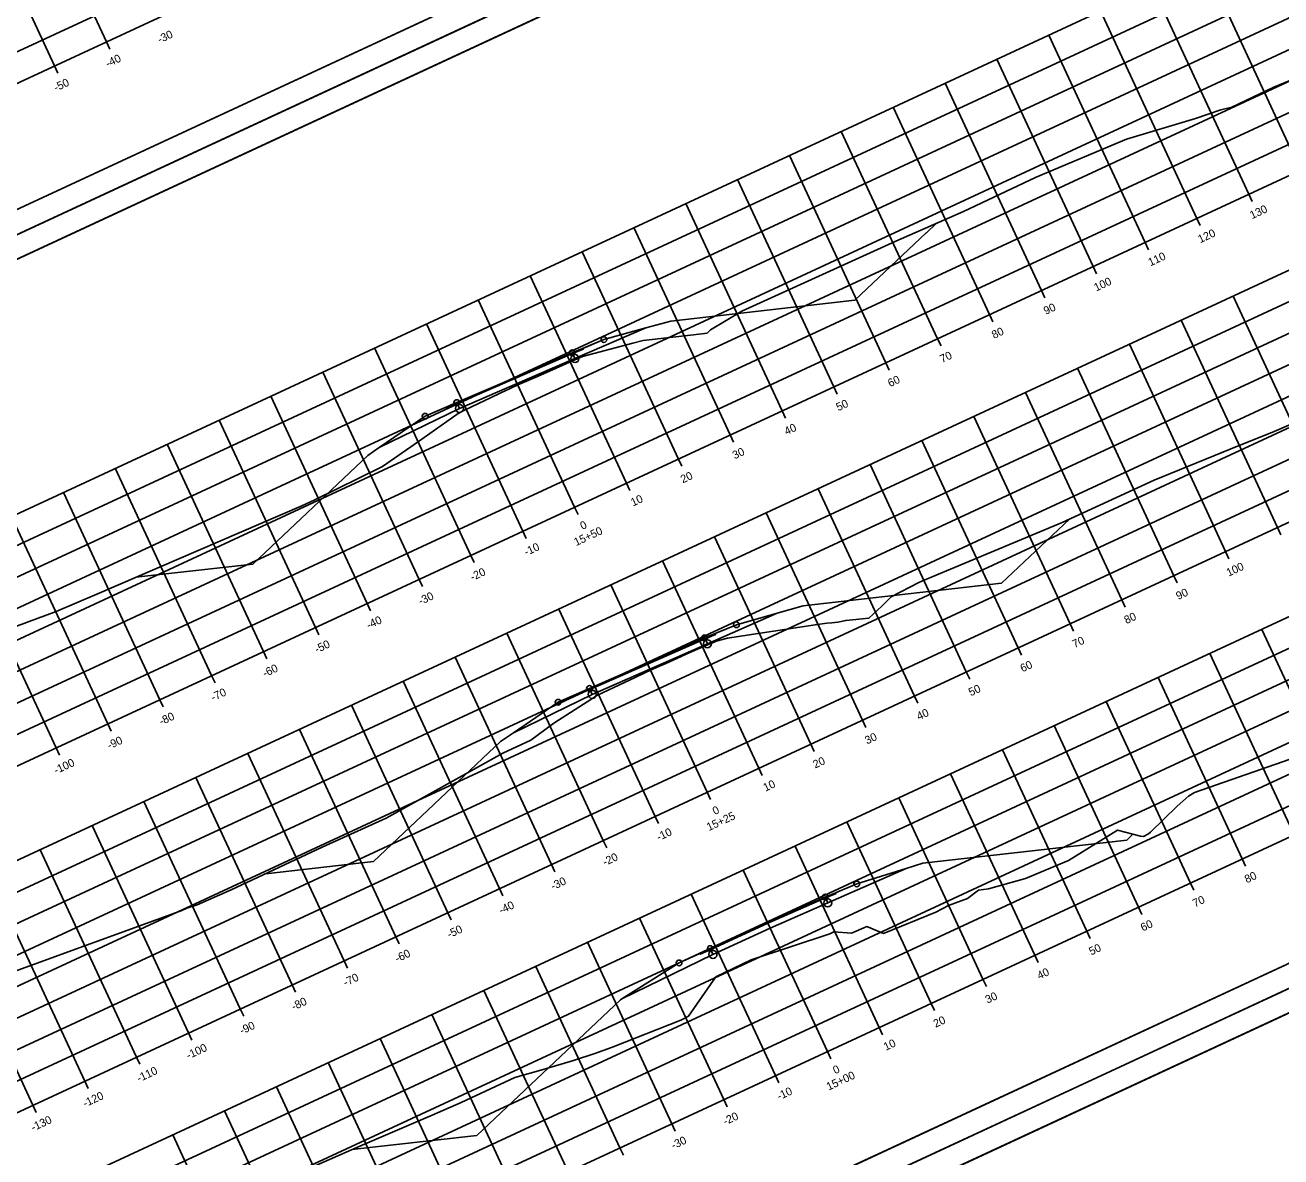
# Model space of a CAD drawing. Extents: x 1354696 to 1366163, y 660729 to 670380.
# Drawn here: x 1358777 to 1358996.6, y 665980.8 to 666178.8 of the extents above; entities that cross this region are included whole.
import ezdxf

# ---------------------------------------------------------------- set-up
doc = ezdxf.new("R2010")
doc.units = 0
for name, color, linetype in [('R_Alt Surface', 7, 'Continuous'), ('R_Axis', 7, 'Continuous'), ('R_Axis Annot', 7, 'Continuous'), ('R_Border', 7, 'Continuous'), ('R_Exist Surface', 7, 'Continuous'), ('R_Fin Surface', 7, 'Continuous'), ('R_Grid', 7, 'Continuous'), ('R_No Plot', 7, 'Continuous')]:
    doc.layers.add(name, color=color, linetype=linetype)

msp = doc.modelspace()

# ---------------------------------------------------------------- linework, layer by layer
at = {"layer": 'R_Alt Surface'}
for p, q in [((1358872.65, 666121.46), (1358874.5, 666122.23)), ((1358872.72, 666121.31), (1358874.57, 666122.08)), ((1358850.62, 666111.95), (1358852.45, 666112.74)), ((1358850.69, 666111.8), (1358852.52, 666112.59)), ((1358895.81, 666071.58), (1358897.66, 666072.34)), ((1358895.88, 666071.42), (1358897.73, 666072.19)), ((1358873.85, 666061.92), (1358875.67, 666062.72)), ((1358873.92, 666061.77), (1358875.74, 666062.57)), ((1358916.87, 666026.22), (1358918.72, 666026.99)), ((1358916.94, 666026.07), (1358918.79, 666026.84)), ((1358894.97, 666016.37), (1358896.8, 666017.21)), ((1358895.04, 666016.22), (1358896.87, 666017.06))]:
    msp.add_line(p, q, dxfattribs=at)
for points in [[(1358838.9, 666104.87), (1358852.92, 666111.72), (1358863.02, 666116.08), (1358873.13, 666120.44), (1358885.55, 666125.8)], [(1358852.45, 666112.74), (1358862.55, 666117.1), (1358872.65, 666121.46)], [(1358852.52, 666112.59), (1358862.62, 666116.95), (1358872.72, 666121.31)], [(1358862.36, 666054.97), (1358876.14, 666061.7), (1358886.21, 666066.13), (1358896.29, 666070.56), (1358908.5, 666075.92)], [(1358875.67, 666062.72), (1358885.74, 666067.15), (1358895.81, 666071.58)], [(1358875.74, 666062.57), (1358885.81, 666067), (1358895.88, 666071.42)], [(1358881.34, 666008.4), (1358897.27, 666016.19), (1358907.27, 666020.77), (1358917.34, 666025.2), (1358931.06, 666031.24)], [(1358896.8, 666017.21), (1358906.8, 666021.79), (1358916.87, 666026.22)], [(1358896.87, 666017.06), (1358906.87, 666021.64), (1358916.94, 666026.07)]]:
    msp.add_lwpolyline(points, dxfattribs=at)
for points in [[(1358874.5, 666122.23), (1358874.57, 666122.08), (1358872.72, 666121.31), (1358873.13, 666120.44), (1358885.55, 666125.8), (1358878.2, 666123.77)], [(1358850.62, 666111.95), (1358850.69, 666111.8), (1358852.52, 666112.59), (1358852.92, 666111.72), (1358838.9, 666104.87), (1358846.93, 666110.36)], [(1358897.66, 666072.34), (1358897.73, 666072.19), (1358895.88, 666071.42), (1358896.29, 666070.56), (1358908.5, 666075.92), (1358901.36, 666073.88)], [(1358873.85, 666061.92), (1358873.92, 666061.77), (1358875.74, 666062.57), (1358876.14, 666061.7), (1358862.36, 666054.97), (1358870.17, 666060.31)], [(1358918.72, 666026.99), (1358922.41, 666028.53), (1358931.06, 666031.24), (1358917.34, 666025.2), (1358916.94, 666026.07), (1358918.79, 666026.84)], [(1358894.97, 666016.37), (1358895.04, 666016.22), (1358896.87, 666017.06), (1358897.27, 666016.19), (1358881.34, 666008.4), (1358891.34, 666014.71)]]:
    msp.add_lwpolyline(points, close=True, dxfattribs=at)
at = {"layer": 'R_Axis'}
for p, q in [((1358691.39, 666129.54), (1358963.5, 666255.87)), ((1358791.76, 666174.59), (1358791.17, 666175.86)), ((1358782.69, 666170.38), (1358782.1, 666171.65)), ((1358737.02, 666031.28), (1359009.12, 666157.61)), ((1358991.57, 666147.92), (1358990.98, 666149.19)), ((1358982.5, 666143.71), (1358981.91, 666144.98)), ((1358973.43, 666139.5), (1358972.84, 666140.77)), ((1358964.36, 666135.28), (1358963.77, 666136.55)), ((1358955.29, 666131.07), (1358954.7, 666132.34)), ((1358946.22, 666126.86), (1358945.63, 666128.13)), ((1358937.15, 666122.65), (1358936.56, 666123.92)), ((1358928.08, 666118.44), (1358927.49, 666119.71)), ((1358919.01, 666114.23), (1358918.42, 666115.5)), ((1358909.94, 666110.02), (1358909.35, 666111.29)), ((1358760.18, 665981.39), (1359032.28, 666107.72)), ((1358900.87, 666105.81), (1358900.28, 666107.08)), ((1358891.8, 666101.6), (1358891.21, 666102.87)), ((1358882.73, 666097.39), (1358882.14, 666098.65)), ((1358873.66, 666093.17), (1358873.07, 666094.44)), ((1358864.59, 666088.96), (1358864, 666090.23)), ((1358996.59, 666089.61), (1358996, 666090.88)), ((1358855.52, 666084.75), (1358854.93, 666086.02)), ((1358987.52, 666085.4), (1358986.93, 666086.67)), ((1358978.45, 666081.19), (1358977.86, 666082.46)), ((1358846.45, 666080.54), (1358845.86, 666081.81)), ((1358969.38, 666076.98), (1358968.79, 666078.25)), ((1358837.38, 666076.33), (1358836.79, 666077.6)), ((1358960.31, 666072.77), (1358959.72, 666074.04)), ((1358828.31, 666072.12), (1358827.72, 666073.39)), ((1358951.24, 666068.55), (1358950.65, 666069.82)), ((1358819.24, 666067.91), (1358818.65, 666069.18)), ((1358810.17, 666063.7), (1358809.58, 666064.97)), ((1358942.17, 666064.34), (1358941.58, 666065.61)), ((1358781.23, 665936.04), (1359053.34, 666062.37)), ((1358801.1, 666059.49), (1358800.51, 666060.76)), ((1358933.1, 666060.13), (1358932.51, 666061.4)), ((1358792.03, 666055.27), (1358791.44, 666056.54)), ((1358924.03, 666055.92), (1358923.44, 666057.19)), ((1358782.96, 666051.06), (1358782.37, 666052.33)), ((1358914.96, 666051.71), (1358914.37, 666052.98)), ((1358905.89, 666047.5), (1358905.3, 666048.77)), ((1358896.82, 666043.29), (1358896.23, 666044.56)), ((1358887.75, 666039.08), (1358887.16, 666040.35)), ((1358878.68, 666034.87), (1358878.09, 666036.14)), ((1358869.61, 666030.66), (1358869.02, 666031.93)), ((1358990.43, 666031.63), (1358989.84, 666032.9)), ((1358860.54, 666026.44), (1358859.95, 666027.71)), ((1358981.36, 666027.41), (1358980.77, 666028.68)), ((1358851.47, 666022.23), (1358850.88, 666023.5)), ((1358972.29, 666023.2), (1358971.7, 666024.47)), ((1358842.4, 666018.02), (1358841.81, 666019.29)), ((1358963.22, 666018.99), (1358962.63, 666020.26)), ((1358833.33, 666013.81), (1358832.74, 666015.08)), ((1358954.15, 666014.78), (1358953.56, 666016.05)), ((1358824.26, 666009.6), (1358823.67, 666010.87)), ((1358945.08, 666010.57), (1358944.49, 666011.84)), ((1358815.19, 666005.39), (1358814.6, 666006.66)), ((1358936.01, 666006.36), (1358935.42, 666007.63)), ((1358926.94, 666002.15), (1358926.35, 666003.42)), ((1358806.12, 666001.18), (1358805.53, 666002.45)), ((1358917.87, 665997.94), (1358917.28, 665999.21)), ((1358797.05, 665996.97), (1358796.46, 665998.24)), ((1358908.8, 665993.73), (1358908.21, 665995)), ((1358787.98, 665992.76), (1358787.39, 665994.03)), ((1358899.73, 665989.52), (1358899.14, 665990.79)), ((1358778.91, 665988.55), (1358778.32, 665989.81)), ((1358890.66, 665985.3), (1358890.07, 665986.57)), ((1358881.59, 665981.09), (1358881, 665982.36))]:
    msp.add_line(p, q, dxfattribs=at)
at = {"layer": 'R_Border'}
for p, q in [((1358979.34, 666241.18), (1358692.56, 666108.03)), ((1358695.88, 666100.89), (1358982.66, 666234.03)), ((1358834.33, 666164.88), (1358834.33, 666164.88)), ((1358834.33, 666164.88), (1358834.33, 666164.88)), ((1359069.18, 666047.68), (1358782.4, 665914.53)), ((1358785.71, 665907.39), (1359072.49, 666040.53))]:
    msp.add_line(p, q, dxfattribs=at)
at = {"layer": 'R_Exist Surface'}
for points in [[(1358738.8, 666060.04), (1358782.36, 666076.2), (1358789.49, 666079.23), (1358825.33, 666094.7), (1358827.64, 666095.74), (1358839.45, 666101.55), (1358845.74, 666105.92), (1358852.71, 666110.84), (1358853.68, 666111.35), (1358853.8, 666111.41), (1358857.36, 666113.09), (1358857.73, 666113.26), (1358858, 666113.39), (1358860.42, 666114.58), (1358860.69, 666114.7), (1358863.15, 666115.83), (1358863.15, 666115.83), (1358863.41, 666115.95), (1358865.9, 666117.04), (1358866.15, 666117.16), (1358868.66, 666118.22), (1358872.16, 666119.83), (1358872.52, 666119.99), (1358872.7, 666120.07), (1358874.44, 666120.79), (1358883.25, 666123.12), (1358885.04, 666123.59), (1358893.85, 666124.6), (1358896.25, 666124.87), (1358896.85, 666125.49), (1358902.34, 666128.75), (1358929.27, 666140.97), (1358941.06, 666146.15), (1358953.8, 666152.18), (1358969.61, 666158.84), (1358981.67, 666162.47), (1358986.08, 666163.98), (1358988.04, 666164.42), (1358995.36, 666167.94), (1358998.36, 666169.14)], [(1358761.71, 666008.36), (1358804.35, 666023.91), (1358805.24, 666024.3), (1358807.07, 666024.89), (1358812.97, 666027.5), (1358828.92, 666034.98), (1358840.09, 666040.03), (1358860.5, 666051.38), (1358865.4, 666053.66), (1358869.43, 666056.66), (1358876.07, 666060.94), (1358876.25, 666061.04), (1358876.94, 666061.48), (1358879.93, 666062.88), (1358880.83, 666063.31), (1358882.89, 666064.3), (1358883.54, 666064.6), (1358885.6, 666065.6), (1358886.25, 666065.89), (1358888.34, 666066.81), (1358889, 666067.1), (1358891.08, 666068.04), (1358891.73, 666068.34), (1358892.71, 666068.79), (1358895.91, 666070.19), (1358897.48, 666070.84), (1358897.84, 666070.99), (1358899.79, 666071.5), (1358915.13, 666073.87), (1358917.19, 666074.18), (1358918.04, 666074.24), (1358919.11, 666074.33), (1358920.48, 666074.62), (1358924.54, 666075.02), (1358926.78, 666077.13), (1358928.42, 666078.78), (1358933.39, 666081.34), (1358933.66, 666081.44), (1358933.7, 666081.44), (1358933.81, 666081.5), (1358934.2, 666081.67), (1358958.33, 666091.76), (1358974.46, 666099.15), (1358987.72, 666104.62), (1358995.42, 666107.7), (1359003.14, 666111.04)], [(1358814.81, 665973.54), (1358835.53, 665982.66), (1358848.14, 665988.09), (1358853.22, 665990.27), (1358862.63, 665994.67), (1358867.54, 665996.07), (1358872.88, 665997.61), (1358876.63, 665998.89), (1358879.53, 665999.89), (1358891.63, 666004.7), (1358892.96, 666005.37), (1358897.79, 666012.26), (1358903.95, 666015.24), (1358917.7, 666019.79), (1358918.39, 666020.13), (1358921.5, 666019.92), (1358923.67, 666020.82), (1358924.16, 666021.06), (1358927.1, 666019.88), (1358936.24, 666023.61), (1358938.44, 666024.73), (1358941.79, 666025.96), (1358943.7, 666027.44), (1358945.46, 666027.7), (1358951.91, 666029.49), (1358959.46, 666032.6), (1358968.02, 666037.92), (1358972.04, 666036.86), (1358972.55, 666036.84), (1358973.47, 666037.31), (1358973.78, 666037.57), (1358978.48, 666042.13), (1358980.42, 666043.91), (1358981.48, 666044.5), (1359000.75, 666051.23)]]:
    msp.add_lwpolyline(points, dxfattribs=at)
at = {"layer": 'R_Fin Surface'}
for points in [[(1358796.34, 666082.18), (1358816.76, 666084.5), (1358836.89, 666103.5), (1358838.9, 666104.87), (1358846.93, 666110.36), (1358852.45, 666112.74), (1358862.55, 666117.1), (1358872.65, 666121.46), (1358878.2, 666123.77), (1358885.55, 666125.8), (1358889.92, 666127.01), (1358922.1, 666130.66), (1358934.58, 666142.43), (1358934.6, 666142.46), (1358936.3, 666144.06)], [(1358818.99, 666030.32), (1358837.9, 666032.47), (1358860.13, 666053.44), (1358862.36, 666054.97), (1358870.17, 666060.31), (1358875.67, 666062.72), (1358885.74, 666067.15), (1358895.81, 666071.58), (1358901.36, 666073.88), (1358908.5, 666075.92), (1358913.04, 666077.21), (1358947.73, 666081.15), (1358959.6, 666092.34)], [(1358834.12, 665982.04), (1358855.94, 665984.51), (1358881.11, 666008.26), (1358881.34, 666008.4), (1358891.34, 666014.71), (1358896.8, 666017.21), (1358906.8, 666021.79), (1358916.87, 666026.22), (1358922.41, 666028.53), (1358931.06, 666031.24), (1358933.96, 666032.15), (1358969.65, 666036.2), (1358970.72, 666037.21)]]:
    msp.add_lwpolyline(points, dxfattribs=at)
at = {"layer": 'R_Grid'}
for p, q in [((1358689.29, 666134.08), (1358961.39, 666260.41)), ((1358691.39, 666129.54), (1358963.5, 666255.87)), ((1358791.17, 666175.86), (1358774.32, 666212.14)), ((1358782.1, 666171.65), (1358765.25, 666207.93)), ((1358720.17, 666067.56), (1358992.28, 666193.89)), ((1358722.28, 666063.02), (1358994.38, 666189.35)), ((1359000.05, 666153.4), (1358983.21, 666189.68)), ((1358724.38, 666058.49), (1358996.49, 666184.82)), ((1358990.98, 666149.19), (1358974.14, 666185.47)), ((1358981.91, 666144.98), (1358965.07, 666181.26)), ((1358726.49, 666053.95), (1358998.59, 666180.28)), ((1358972.84, 666140.77), (1358956, 666177.05)), ((1358728.59, 666049.42), (1359000.7, 666175.75)), ((1358963.77, 666136.55), (1358946.93, 666172.83)), ((1358730.7, 666044.88), (1359002.8, 666171.21)), ((1358954.7, 666132.34), (1358937.86, 666168.62)), ((1358732.8, 666040.35), (1359004.91, 666166.68)), ((1358945.63, 666128.13), (1358928.78, 666164.41)), ((1358734.91, 666035.81), (1359007.01, 666162.14)), ((1358936.56, 666123.92), (1358919.71, 666160.2)), ((1358737.02, 666031.28), (1359009.12, 666157.61)), ((1358927.49, 666119.71), (1358910.64, 666155.99)), ((1358918.42, 666115.5), (1358901.57, 666151.78)), ((1358909.35, 666111.29), (1358892.5, 666147.57)), ((1358743.33, 666017.67), (1359015.44, 666144)), ((1358900.28, 666107.08), (1358883.43, 666143.36)), ((1358745.44, 666013.14), (1359017.54, 666139.47)), ((1358891.21, 666102.87), (1358874.36, 666139.15)), ((1358747.54, 666008.6), (1359019.65, 666134.93)), ((1358882.14, 666098.65), (1358865.29, 666134.94)), ((1359005.07, 666095.09), (1358988.23, 666131.37)), ((1358749.65, 666004.07), (1359021.75, 666130.4)), ((1358873.07, 666094.44), (1358856.22, 666130.72)), ((1358864, 666090.23), (1358847.15, 666126.51)), ((1358996, 666090.88), (1358979.16, 666127.16)), ((1358751.75, 665999.53), (1359023.86, 666125.86)), ((1358854.93, 666086.02), (1358838.08, 666122.3)), ((1358986.93, 666086.67), (1358970.09, 666122.95)), ((1358753.86, 665995), (1359025.96, 666121.33)), ((1358845.86, 666081.81), (1358829.01, 666118.09)), ((1358977.86, 666082.46), (1358961.02, 666118.74)), ((1358755.97, 665990.46), (1359028.07, 666116.79)), ((1358836.79, 666077.6), (1358819.94, 666113.88)), ((1358968.79, 666078.25), (1358951.95, 666114.53)), ((1358758.07, 665985.93), (1359030.17, 666112.26)), ((1358827.72, 666073.39), (1358810.87, 666109.67)), ((1358959.72, 666074.04), (1358942.88, 666110.32)), ((1358760.18, 665981.39), (1359032.28, 666107.72)), ((1358818.65, 666069.18), (1358801.8, 666105.46)), ((1358950.65, 666069.82), (1358933.81, 666106.1)), ((1358809.58, 666064.97), (1358792.73, 666101.25)), ((1358941.58, 666065.61), (1358924.74, 666101.89)), ((1358800.51, 666060.76), (1358783.66, 666097.04)), ((1358932.51, 666061.4), (1358915.66, 666097.68)), ((1358766.49, 665967.79), (1359038.6, 666094.12)), ((1358923.44, 666057.19), (1358906.59, 666093.47)), ((1358791.44, 666056.54), (1358774.59, 666092.83)), ((1358768.6, 665963.25), (1359040.7, 666089.58)), ((1358914.37, 666052.98), (1358897.52, 666089.26)), ((1358782.37, 666052.33), (1358765.52, 666088.61)), ((1358770.7, 665958.72), (1359042.81, 666085.05)), ((1358905.3, 666048.77), (1358888.45, 666085.05)), ((1358772.81, 665954.18), (1359044.91, 666080.51)), ((1358896.23, 666044.56), (1358879.38, 666080.84)), ((1358774.92, 665949.65), (1359047.02, 666075.98)), ((1358887.16, 666040.35), (1358870.31, 666076.63)), ((1358777.02, 665945.11), (1359049.12, 666071.44)), ((1358878.09, 666036.14), (1358861.24, 666072.42)), ((1359007.98, 666041.32), (1358993.25, 666073.06)), ((1358869.02, 666031.93), (1358852.17, 666068.21)), ((1358998.91, 666037.11), (1358984.18, 666068.85)), ((1358779.13, 665940.58), (1359051.23, 666066.91)), ((1358859.95, 666027.71), (1358843.1, 666063.99)), ((1358989.84, 666032.9), (1358975.11, 666064.64)), ((1358781.23, 665936.04), (1359053.34, 666062.37)), ((1358850.88, 666023.5), (1358834.03, 666059.78)), ((1358980.77, 666028.68), (1358966.04, 666060.43)), ((1358971.7, 666024.47), (1358956.97, 666056.22)), ((1358841.81, 666019.29), (1358824.96, 666055.57)), ((1358962.63, 666020.26), (1358947.9, 666052.01)), ((1358832.74, 666015.08), (1358815.89, 666051.36)), ((1358953.56, 666016.05), (1358938.83, 666047.8)), ((1358823.67, 666010.87), (1358806.82, 666047.15)), ((1358814.6, 666006.66), (1358797.75, 666042.94)), ((1358944.49, 666011.84), (1358929.76, 666043.59)), ((1358805.53, 666002.45), (1358788.68, 666038.73)), ((1358935.42, 666007.63), (1358920.69, 666039.38)), ((1358796.46, 665998.24), (1358779.61, 666034.52)), ((1358926.35, 666003.42), (1358911.62, 666035.16)), ((1358787.39, 665994.03), (1358770.54, 666030.31)), ((1358917.28, 665999.21), (1358902.55, 666030.95)), ((1358778.32, 665989.81), (1358761.47, 666026.1)), ((1358908.21, 665995), (1358893.47, 666026.74)), ((1358899.14, 665990.79), (1358884.4, 666022.53)), ((1358890.07, 665986.57), (1358875.33, 666018.32)), ((1358881, 665982.36), (1358866.26, 666014.11)), ((1358871.93, 665978.15), (1358857.19, 666009.9)), ((1358862.86, 665973.94), (1358848.12, 666005.69)), ((1358853.79, 665969.73), (1358839.05, 666001.48)), ((1358844.72, 665965.52), (1358829.98, 665997.26)), ((1358835.65, 665961.31), (1358820.91, 665993.05)), ((1358826.58, 665957.1), (1358811.84, 665988.84)), ((1358817.51, 665952.89), (1358802.77, 665984.63))]:
    msp.add_line(p, q, dxfattribs=at)
at = {"layer": 'R_No Plot'}
for p, q in [((1358682.99, 666099.2), (1358985.33, 666239.57)), ((1358682.99, 666099.2), (1358985.33, 666239.57)), ((1358772.83, 665905.7), (1359075.16, 666046.07)), ((1358772.83, 665905.7), (1359075.16, 666046.07))]:
    msp.add_line(p, q, dxfattribs=at)
for points in [[(1358593.15, 666292.7), (1358895.49, 666433.07), (1358985.33, 666239.57), (1358682.98, 666099.2)], [(1358818.21, 666392.89), (1358836.01, 666401.15), (1358840.17, 666392.19), (1358854.78, 666398.98), (1358875.82, 666408.75), (1358887.79, 666383.26), (1358908.84, 666393.03), (1358979.34, 666241.18), (1358692.56, 666108.03), (1358606.04, 666294.39)], [(1358682.98, 666099.2), (1358985.33, 666239.57), (1359075.16, 666046.07), (1358772.82, 665905.7)], [(1358908.05, 666199.39), (1358925.84, 666207.65), (1358930, 666198.69), (1358944.62, 666205.48), (1358965.66, 666215.25), (1358977.62, 666189.76), (1358998.67, 666199.53), (1359069.18, 666047.68), (1358782.4, 665914.53), (1358695.88, 666100.89)], [(1358772.82, 665905.7), (1359075.16, 666046.07), (1359165, 665852.57), (1358862.66, 665712.2)], [(1358997.88, 666005.89), (1359015.68, 666014.15), (1359019.84, 666005.19), (1359034.45, 666011.98), (1359055.5, 666021.75), (1359067.46, 665996.26), (1359088.51, 666006.03), (1359159.01, 665854.18), (1358872.23, 665721.03), (1358785.71, 665907.39)]]:
    msp.add_lwpolyline(points, close=True, dxfattribs=at)
for centre, radius in [((1358878.2, 666123.77), 0.5), ((1358872.65, 666121.46), 0.5), ((1358873.13, 666120.44), 0.7), ((1358852.45, 666112.74), 0.5), ((1358852.92, 666111.72), 0.7), ((1358846.93, 666110.36), 0.5), ((1358901.36, 666073.88), 0.5), ((1358895.81, 666071.58), 0.5), ((1358896.29, 666070.56), 0.7), ((1358875.67, 666062.72), 0.5), ((1358870.17, 666060.31), 0.5), ((1358876.14, 666061.7), 0.7), ((1358922.41, 666028.53), 0.5), ((1358916.87, 666026.22), 0.5), ((1358917.34, 666025.2), 0.7), ((1358896.8, 666017.21), 0.5), ((1358897.27, 666016.19), 0.7), ((1358891.34, 666014.71), 0.5)]:
    msp.add_circle(centre, radius, dxfattribs=at)

# ---------------------------------------------------------------- texts
at = {"layer": 'R_Axis Annot'}
for s, p in [('-30', (1358800.5, 666175.57)), ('-40', (1358791.43, 666171.36)), ('-50', (1358782.36, 666167.14)), ('130', (1358991.55, 666144.82)), ('120', (1358982.48, 666140.61)), ('110', (1358973.77, 666136.57)), ('100', (1358964.29, 666132.17)), ('90', (1358955.48, 666128.08)), ('80', (1358946.41, 666123.87)), ('70', (1358937.34, 666119.65)), ('60', (1358928.24, 666115.43)), ('50', (1358919.2, 666111.23)), ('40', (1358910.13, 666107.02)), ('30', (1358901.06, 666102.81)), ('20', (1358891.99, 666098.6)), ('10', (1358883.28, 666094.56)), ('0', (1358874.42, 666090.44)), ('15+50', (1358873.34, 666087.62)), ('-10', (1358864.62, 666085.89)), ('100', (1358987.45, 666082.28)), ('-20', (1358855.19, 666081.51)), ('90', (1358978.64, 666078.19)), ('-30', (1358846.12, 666077.3)), ('80', (1358969.57, 666073.98)), ('-40', (1358837.05, 666073.09)), ('70', (1358960.5, 666069.77)), ('-50', (1358827.98, 666068.88)), ('60', (1358951.4, 666065.54)), ('-60', (1358818.88, 666064.66)), ('-70', (1358809.84, 666060.46)), ('50', (1358942.36, 666061.35)), ('-80', (1358800.77, 666056.25)), ('40', (1358933.29, 666057.14)), ('-90', (1358791.7, 666052.04)), ('30', (1358924.22, 666052.92)), ('-100', (1358782.37, 666047.7)), ('20', (1358915.15, 666048.71)), ('10', (1358906.44, 666044.67)), ('15+25', (1358896.55, 666037.76)), ('0', (1358897.58, 666040.56)), ('-10', (1358887.78, 666036.01)), ('-20', (1358878.35, 666031.63)), ('-30', (1358869.28, 666027.42)), ('80', (1358990.63, 666028.63)), ('-40', (1358860.21, 666023.21)), ('70', (1358981.56, 666024.42)), ('-50', (1358851.14, 666019)), ('60', (1358972.46, 666020.19)), ('-60', (1358842.04, 666014.77)), ('50', (1358963.42, 666016)), ('-70', (1358833, 666010.57)), ('40', (1358954.35, 666011.78)), ('-80', (1358823.93, 666006.36)), ('30', (1358945.28, 666007.57)), ('-90', (1358814.86, 666002.15)), ('20', (1358936.21, 666003.36)), ('10', (1358927.5, 665999.32)), ('-100', (1358805.53, 665997.82)), ('0', (1358918.64, 665995.21)), ('-110', (1358796.87, 665993.8)), ('15+00', (1358917.5, 665992.36)), ('-10', (1358908.84, 665990.66)), ('-120', (1358787.44, 665989.42)), ('-20', (1358899.41, 665986.28)), ('-130', (1358778.37, 665985.21)), ('-30', (1358890.34, 665982.07))]:
    msp.add_text(s, height=1.4, rotation=24.9042, dxfattribs=at).set_placement(p)

doc.saveas('drawing.dxf')
